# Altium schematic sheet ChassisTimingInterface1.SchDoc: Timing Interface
size B; Engineer: Daniel Sigg; DocumentNumber: 1; Revision: C; SheetNumber: 1; SheetTotal: 12; PageSetup: Record=PageOptions¦CenterHorizontal=True¦CenterVertical=True¦PrintScale=0.72¦XCorrection=1.00¦YCorrection=1.00¦PrintKind=0¦BorderSize=5000000¦LeftOffset=0¦BottomOffset=0¦Orientation=2¦PaperLength=1000¦PaperWidth=1000¦Scale=100¦PaperSource=7¦PrintQuality=-4¦MediaType=1¦DitherType=10¦PaperKind=Tabloid¦PrintScaleMode=1
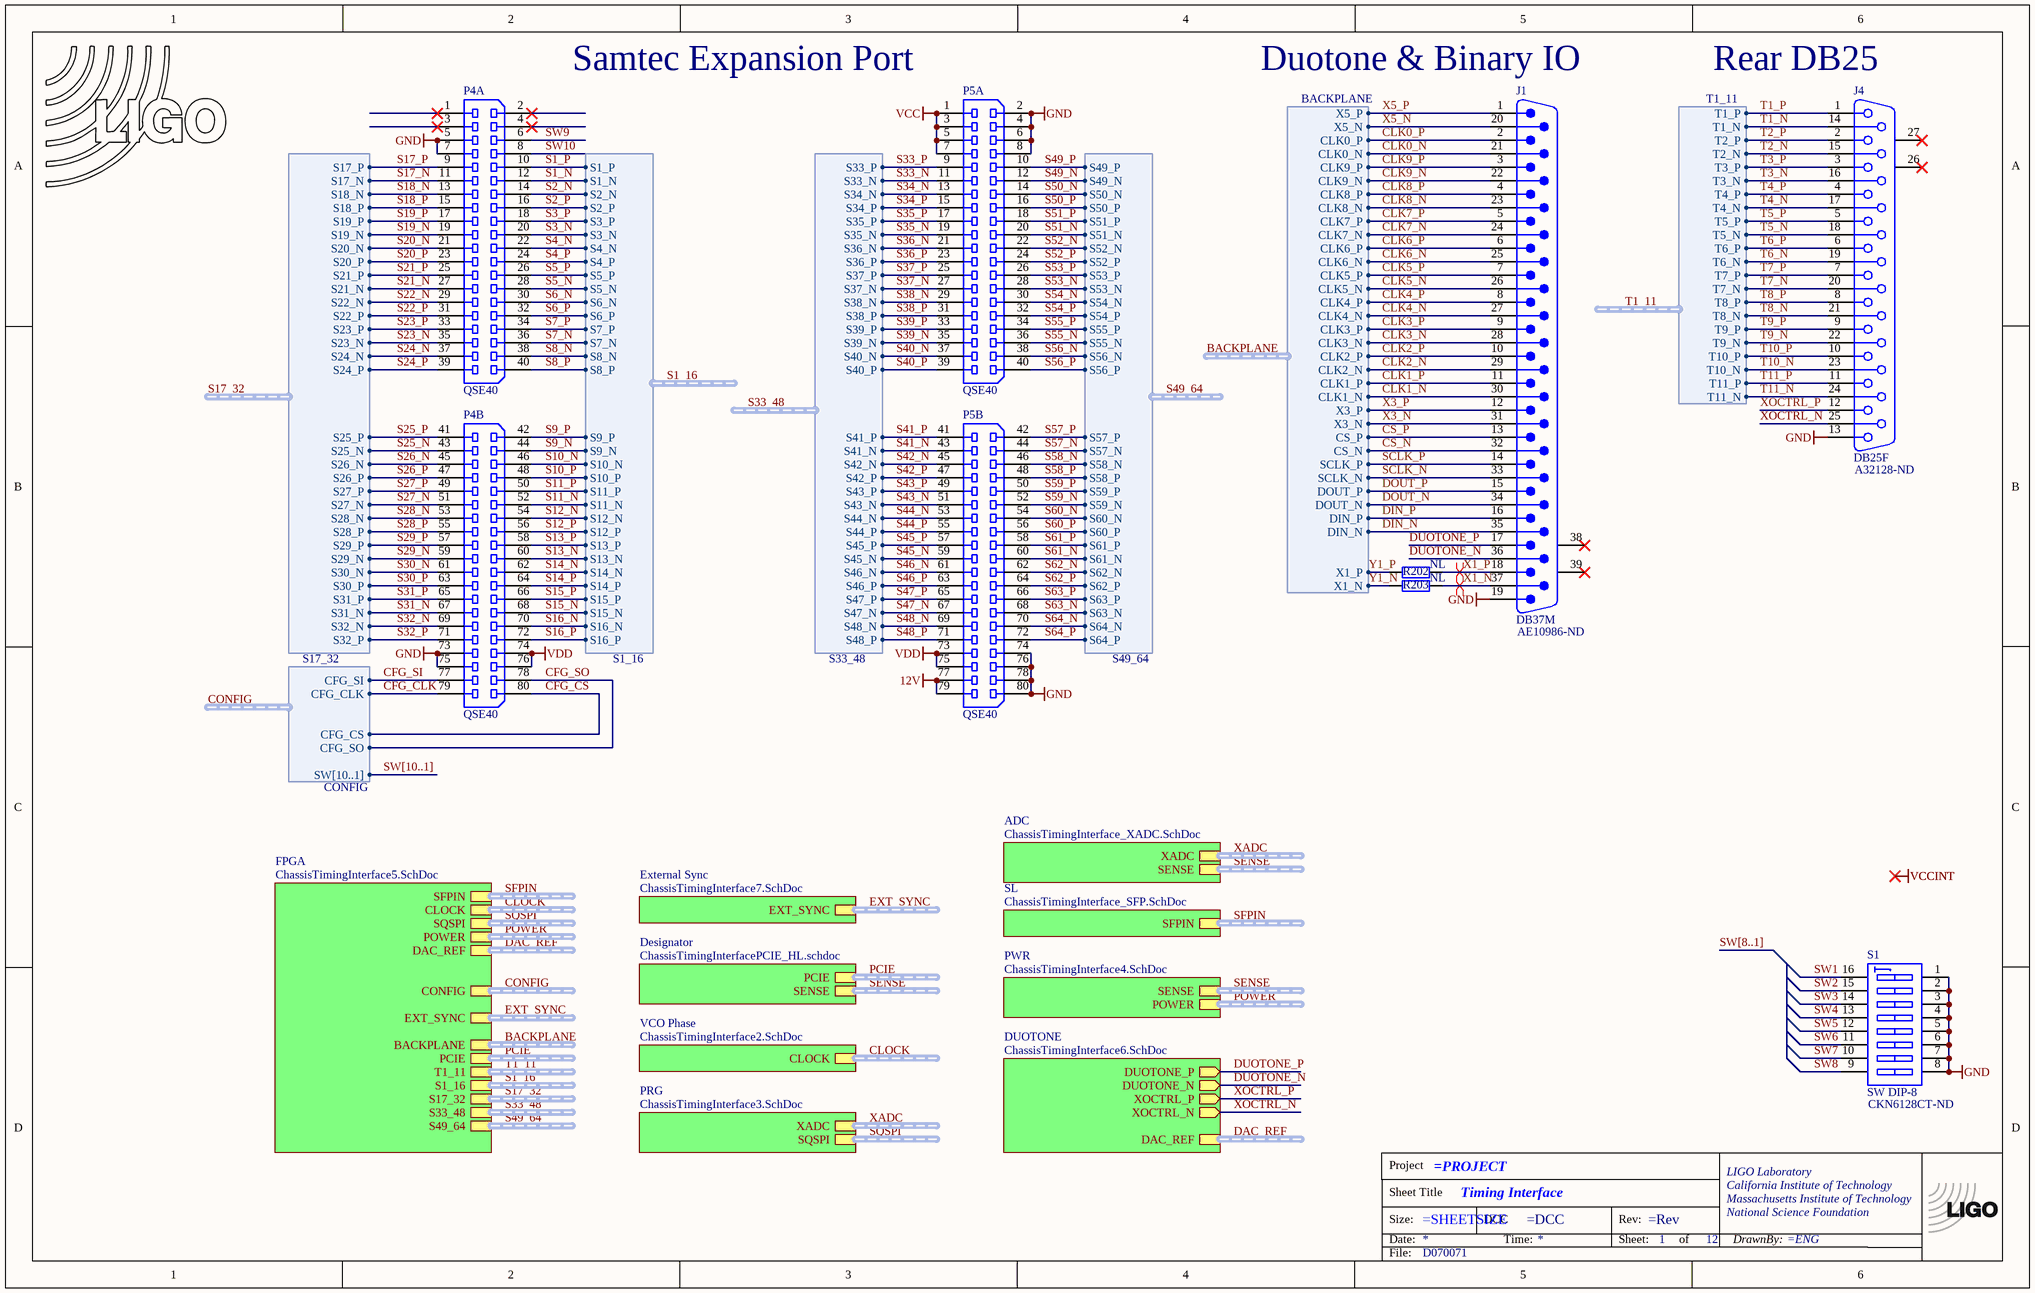
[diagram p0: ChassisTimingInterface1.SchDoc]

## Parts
*  TitleBlock  (value not drawn)  (graphical)
J1  DB37M  Supplier Part Number 1: AE10986-ND  [DB37M-RA]
J4  DB25F  Supplier Part Number 1: A32128-ND  [DB25F-RA]
LOGO1  LIGO logo  [LIGO-LOGO-SM]  (value not drawn)  (no BOM)
P4  QSE40  [QSE040]  (parts A,B of 2)
P5  QSE40  [QSE040]  (parts A,B of 2)
R202  NL  [CR1005-0402]
R203  NL  [CR1005-0402]
S1  SW DIP-8  Supplier Part Number 1: CKN6128CT-ND  [DIP_SW_8WAY_SMD_SIDE]

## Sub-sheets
ADC = ChassisTimingInterface_XADC.SchDoc: XADC (harness XADC), SENSE (harness SENSE)
Designator = ChassisTimingInterfacePCIE_HL.schdoc: PCIE (harness PCIE), SENSE (harness SENSE)
DUOTONE = ChassisTimingInterface6.SchDoc: DUOTONE_N (out), DUOTONE_P (out), XOCTRL_P (out), XOCTRL_N (out), DAC_REF (harness DAC_REF)
External Sync = ChassisTimingInterface7.SchDoc: EXT_SYNC (harness EXT_SYNC)
FPGA = ChassisTimingInterface5.SchDoc: S1_16 (harness S1_16), S17_32 (harness S17_32), S33_48 (harness S33_48), S49_64 (harness S49_64), T1_11 (harness T1_11), CLOCK (harness CLOCK), PCIE (harness PCIE), POWER (harness POWER), SQSPI (harness SQSPI), DAC_REF (harness DAC_REF), CONFIG (harness CONFIG), BACKPLANE (harness BACKPLANE), SFPIN (harness SFPIN), EXT_SYNC (harness EXT_SYNC)
PRG = ChassisTimingInterface3.SchDoc: SQSPI (harness SQSPI), XADC (harness XADC)
PWR = ChassisTimingInterface4.SchDoc: POWER (harness POWER), SENSE (harness SENSE)
SL = ChassisTimingInterface_SFP.SchDoc: SFPIN (harness SFPIN)
VCO Phase = ChassisTimingInterface2.SchDoc: CLOCK (harness CLOCK)

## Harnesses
S1_16: S1_N, S1_P, S2_N, S2_P, S3_N, S3_P, S4_N, S4_P, S5_N, S5_P, S6_N, S6_P, S7_N, S7_P, S8_N, S8_P, S9_N, S9_P, S10_N, S10_P, S11_N, S11_P, S12_N, S12_P, S13_N, S13_P, S14_N, S14_P, S15_N, S15_P, S16_N, S16_P
S17_32: S17_N, S17_P, S18_N, S18_P, S19_N, S19_P, S20_N, S20_P, S21_N, S21_P, S22_N, S22_P, S23_N, S23_P, S24_N, S24_P, S25_N, S25_P, S26_N, S26_P, S27_N, S27_P, S28_N, S28_P, S29_N, S29_P, S30_N, S30_P, S31_N, S31_P, S32_N, S32_P
S33_48: S33_P, S33_N, S34_P, S34_N, S35_P, S35_N, S36_N, S36_P, S37_P, S37_N, S38_N, S38_P, S39_P, S39_N, S40_N, S40_P, S41_P, S41_N, S42_N, S42_P, S43_P, S43_N, S44_N, S44_P, S45_P, S45_N, S46_N, S46_P, S47_P, S47_N, S48_N, S48_P
S49_64: S49_P, S49_N, S50_N, S50_P, S51_P, S51_N, S52_N, S52_P, S53_P, S53_N, S54_N, S54_P, S55_P, S55_N, S56_N, S56_P, S57_P, S57_N, S58_N, S58_P, S59_P, S59_N, S60_N, S60_P, S61_P, S61_N, S62_N, S62_P, S63_P, S63_N, S64_N, S64_P
T1_11: T1_P, T1_N, T2_P, T2_N, T3_P, T3_N, T4_P, T4_N, T5_P, T5_N, T6_P, T6_N, T7_P, T7_N, T8_P, T8_N, T9_P, T9_N, T10_P, T10_N, T11_P, T11_N
CONFIG: CFG_CLK, CFG_CS, CFG_SI, CFG_SO, SW[10..1]
BACKPLANE: DIN_N, DIN_P, DOUT_N, DOUT_P, SCLK_N, SCLK_P, CS_N, CS_P, X3_N, X3_P, CLK1_N, CLK1_P, CLK2_N, CLK2_P, CLK3_N, CLK3_P, CLK4_N, CLK4_P, CLK5_N, CLK5_P, CLK6_N, CLK6_P, CLK7_N, CLK7_P, CLK8_N, CLK8_P, CLK9_N, CLK9_P, CLK0_N, CLK0_P, X5_N, X5_P, X1_P, X1_N

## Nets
12V: P5.77 P5.79
GND: J1.19 J4.13 P4.5 P4.7 P4.73 P4.75 P4.81 P4.82 P4.83 P4.84 P4.85 P4.86 P4.87 P4.88 P5.2 P5.4 P5.6 P5.8 P5.74 P5.76 P5.78 P5.80 P5.81 P5.82 P5.83 P5.84 P5.85 P5.86 P5.87 P5.88 S1.1(A1) S1.2(A2) S1.3(A3) S1.4(A4) S1.5(A5) S1.6(A6) S1.7(A7) S1.8(A8)
VCC: P5.1 P5.3 P5.5 P5.7
VDD: P4.74 P4.76 P5.73 P5.75
CFG_CLK: P4.79 ; sheet FPGA/CONFIG.CFG_CLK
CFG_CS: P4.80 ; sheet FPGA/CONFIG.CFG_CS
CFG_SI: P4.77 ; sheet FPGA/CONFIG.CFG_SI
CFG_SO: P4.78 ; sheet FPGA/CONFIG.CFG_SO
CLK0_N: J1.21 ; sheet FPGA/BACKPLANE.CLK0_N  [project net BACKPLANE.CLK0_N]
CLK0_P: J1.2 ; sheet FPGA/BACKPLANE.CLK0_P  [project net BACKPLANE.CLK0_P]
CLK1_N: J1.30 ; sheet FPGA/BACKPLANE.CLK1_N  [project net BACKPLANE.CLK1_N]
CLK1_P: J1.11 ; sheet FPGA/BACKPLANE.CLK1_P  [project net BACKPLANE.CLK1_P]
CLK2_N: J1.29 ; sheet FPGA/BACKPLANE.CLK2_N  [project net BACKPLANE.CLK2_N]
CLK2_P: J1.10 ; sheet FPGA/BACKPLANE.CLK2_P  [project net BACKPLANE.CLK2_P]
CLK3_N: J1.28 ; sheet FPGA/BACKPLANE.CLK3_N  [project net BACKPLANE.CLK3_N]
CLK3_P: J1.9 ; sheet FPGA/BACKPLANE.CLK3_P  [project net BACKPLANE.CLK3_P]
CLK4_N: J1.27 ; sheet FPGA/BACKPLANE.CLK4_N  [project net BACKPLANE.CLK4_N]
CLK4_P: J1.8 ; sheet FPGA/BACKPLANE.CLK4_P  [project net BACKPLANE.CLK4_P]
CLK5_N: J1.26 ; sheet FPGA/BACKPLANE.CLK5_N  [project net BACKPLANE.CLK5_N]
CLK5_P: J1.7 ; sheet FPGA/BACKPLANE.CLK5_P  [project net BACKPLANE.CLK5_P]
CLK6_N: J1.25 ; sheet FPGA/BACKPLANE.CLK6_N  [project net BACKPLANE.CLK6_N]
CLK6_P: J1.6 ; sheet FPGA/BACKPLANE.CLK6_P  [project net BACKPLANE.CLK6_P]
CLK7_N: J1.24 ; sheet FPGA/BACKPLANE.CLK7_N  [project net BACKPLANE.CLK7_N]
CLK7_P: J1.5 ; sheet FPGA/BACKPLANE.CLK7_P  [project net BACKPLANE.CLK7_P]
CLK8_N: J1.23 ; sheet FPGA/BACKPLANE.CLK8_N  [project net BACKPLANE.CLK8_N]
CLK8_P: J1.4 ; sheet FPGA/BACKPLANE.CLK8_P  [project net BACKPLANE.CLK8_P]
CLK9_N: J1.22 ; sheet FPGA/BACKPLANE.CLK9_N  [project net BACKPLANE.CLK9_N]
CLK9_P: J1.3 ; sheet FPGA/BACKPLANE.CLK9_P  [project net BACKPLANE.CLK9_P]
CS_N: J1.32 ; sheet FPGA/BACKPLANE.CS_N  [project net BACKPLANE.CS_N]
CS_P: J1.13 ; sheet FPGA/BACKPLANE.CS_P  [project net BACKPLANE.CS_P]
DIN_N: J1.35 ; sheet FPGA/BACKPLANE.DIN_N  [project net BACKPLANE.DIN_N]
DIN_P: J1.16 ; sheet FPGA/BACKPLANE.DIN_P  [project net BACKPLANE.DIN_P]
DOUT_N: J1.34 ; sheet FPGA/BACKPLANE.DOUT_N  [project net BACKPLANE.DOUT_N]
DOUT_P: J1.15 ; sheet FPGA/BACKPLANE.DOUT_P  [project net BACKPLANE.DOUT_P]
DUOTONE_N: J1.36 ; sheet DUOTONE/DUOTONE_N
DUOTONE_P: J1.17 ; sheet DUOTONE/DUOTONE_P
S1_N: P4.12 ; sheet FPGA/S1_16.S1_N  [project net S1_16.S1_N]
S1_P: P4.10 ; sheet FPGA/S1_16.S1_P  [project net S1_16.S1_P]
S2_N: P4.14 ; sheet FPGA/S1_16.S2_N  [project net S1_16.S2_N]
S2_P: P4.16 ; sheet FPGA/S1_16.S2_P  [project net S1_16.S2_P]
S3_N: P4.20 ; sheet FPGA/S1_16.S3_N  [project net S1_16.S3_N]
S3_P: P4.18 ; sheet FPGA/S1_16.S3_P  [project net S1_16.S3_P]
S4_N: P4.22 ; sheet FPGA/S1_16.S4_N  [project net S1_16.S4_N]
S4_P: P4.24 ; sheet FPGA/S1_16.S4_P  [project net S1_16.S4_P]
S5_N: P4.28 ; sheet FPGA/S1_16.S5_N  [project net S1_16.S5_N]
S5_P: P4.26 ; sheet FPGA/S1_16.S5_P  [project net S1_16.S5_P]
S6_N: P4.30 ; sheet FPGA/S1_16.S6_N  [project net S1_16.S6_N]
S6_P: P4.32 ; sheet FPGA/S1_16.S6_P  [project net S1_16.S6_P]
S7_N: P4.36 ; sheet FPGA/S1_16.S7_N  [project net S1_16.S7_N]
S7_P: P4.34 ; sheet FPGA/S1_16.S7_P  [project net S1_16.S7_P]
S8_N: P4.38 ; sheet FPGA/S1_16.S8_N  [project net S1_16.S8_N]
S8_P: P4.40 ; sheet FPGA/S1_16.S8_P  [project net S1_16.S8_P]
S9_N: P4.44 ; sheet FPGA/S1_16.S9_N  [project net S1_16.S9_N]
S9_P: P4.42 ; sheet FPGA/S1_16.S9_P  [project net S1_16.S9_P]
S10_N: P4.46 ; sheet FPGA/S1_16.S10_N
S10_P: P4.48 ; sheet FPGA/S1_16.S10_P
S11_N: P4.52 ; sheet FPGA/S1_16.S11_N
S11_P: P4.50 ; sheet FPGA/S1_16.S11_P
S12_N: P4.54 ; sheet FPGA/S1_16.S12_N
S12_P: P4.56 ; sheet FPGA/S1_16.S12_P
S13_N: P4.60 ; sheet FPGA/S1_16.S13_N
S13_P: P4.58 ; sheet FPGA/S1_16.S13_P
S14_N: P4.62 ; sheet FPGA/S1_16.S14_N
S14_P: P4.64 ; sheet FPGA/S1_16.S14_P
S15_N: P4.68 ; sheet FPGA/S1_16.S15_N
S15_P: P4.66 ; sheet FPGA/S1_16.S15_P
S16_N: P4.70 ; sheet FPGA/S1_16.S16_N
S16_P: P4.72 ; sheet FPGA/S1_16.S16_P
S17_N: P4.11 ; sheet FPGA/S17_32.S17_N  [project net S17_32.S17_N]
S17_P: P4.9 ; sheet FPGA/S17_32.S17_P  [project net S17_32.S17_P]
S18_N: P4.13 ; sheet FPGA/S17_32.S18_N  [project net S17_32.S18_N]
S18_P: P4.15 ; sheet FPGA/S17_32.S18_P  [project net S17_32.S18_P]
S19_N: P4.19 ; sheet FPGA/S17_32.S19_N  [project net S17_32.S19_N]
S19_P: P4.17 ; sheet FPGA/S17_32.S19_P  [project net S17_32.S19_P]
S20_N: P4.21 ; sheet FPGA/S17_32.S20_N  [project net S17_32.S20_N]
S20_P: P4.23 ; sheet FPGA/S17_32.S20_P  [project net S17_32.S20_P]
S21_N: P4.27 ; sheet FPGA/S17_32.S21_N  [project net S17_32.S21_N]
S21_P: P4.25 ; sheet FPGA/S17_32.S21_P  [project net S17_32.S21_P]
S22_N: P4.29 ; sheet FPGA/S17_32.S22_N  [project net S17_32.S22_N]
S22_P: P4.31 ; sheet FPGA/S17_32.S22_P  [project net S17_32.S22_P]
S23_N: P4.35 ; sheet FPGA/S17_32.S23_N  [project net S17_32.S23_N]
S23_P: P4.33 ; sheet FPGA/S17_32.S23_P  [project net S17_32.S23_P]
S24_N: P4.37 ; sheet FPGA/S17_32.S24_N  [project net S17_32.S24_N]
S24_P: P4.39 ; sheet FPGA/S17_32.S24_P  [project net S17_32.S24_P]
S25_N: P4.43 ; sheet FPGA/S17_32.S25_N  [project net S17_32.S25_N]
S25_P: P4.41 ; sheet FPGA/S17_32.S25_P  [project net S17_32.S25_P]
S26_N: P4.45 ; sheet FPGA/S17_32.S26_N  [project net S17_32.S26_N]
S26_P: P4.47 ; sheet FPGA/S17_32.S26_P  [project net S17_32.S26_P]
S27_N: P4.51 ; sheet FPGA/S17_32.S27_N  [project net S17_32.S27_N]
S27_P: P4.49 ; sheet FPGA/S17_32.S27_P  [project net S17_32.S27_P]
S28_N: P4.53 ; sheet FPGA/S17_32.S28_N  [project net S17_32.S28_N]
S28_P: P4.55 ; sheet FPGA/S17_32.S28_P  [project net S17_32.S28_P]
S29_N: P4.59 ; sheet FPGA/S17_32.S29_N  [project net S17_32.S29_N]
S29_P: P4.57 ; sheet FPGA/S17_32.S29_P  [project net S17_32.S29_P]
S30_N: P4.61 ; sheet FPGA/S17_32.S30_N  [project net S17_32.S30_N]
S30_P: P4.63 ; sheet FPGA/S17_32.S30_P  [project net S17_32.S30_P]
S31_N: P4.67 ; sheet FPGA/S17_32.S31_N  [project net S17_32.S31_N]
S31_P: P4.65 ; sheet FPGA/S17_32.S31_P  [project net S17_32.S31_P]
S32_N: P4.69 ; sheet FPGA/S17_32.S32_N  [project net S17_32.S32_N]
S32_P: P4.71 ; sheet FPGA/S17_32.S32_P  [project net S17_32.S32_P]
S33_N: P5.11 ; sheet FPGA/S33_48.S33_N  [project net S33_48.S33_N]
S33_P: P5.9 ; sheet FPGA/S33_48.S33_P  [project net S33_48.S33_P]
S34_N: P5.13 ; sheet FPGA/S33_48.S34_N  [project net S33_48.S34_N]
S34_P: P5.15 ; sheet FPGA/S33_48.S34_P  [project net S33_48.S34_P]
S35_N: P5.19 ; sheet FPGA/S33_48.S35_N  [project net S33_48.S35_N]
S35_P: P5.17 ; sheet FPGA/S33_48.S35_P  [project net S33_48.S35_P]
S36_N: P5.21 ; sheet FPGA/S33_48.S36_N  [project net S33_48.S36_N]
S36_P: P5.23 ; sheet FPGA/S33_48.S36_P  [project net S33_48.S36_P]
S37_N: P5.27 ; sheet FPGA/S33_48.S37_N  [project net S33_48.S37_N]
S37_P: P5.25 ; sheet FPGA/S33_48.S37_P  [project net S33_48.S37_P]
S38_N: P5.29 ; sheet FPGA/S33_48.S38_N  [project net S33_48.S38_N]
S38_P: P5.31 ; sheet FPGA/S33_48.S38_P  [project net S33_48.S38_P]
S39_N: P5.35 ; sheet FPGA/S33_48.S39_N  [project net S33_48.S39_N]
S39_P: P5.33 ; sheet FPGA/S33_48.S39_P  [project net S33_48.S39_P]
S40_N: P5.37 ; sheet FPGA/S33_48.S40_N  [project net S33_48.S40_N]
S40_P: P5.39 ; sheet FPGA/S33_48.S40_P  [project net S33_48.S40_P]
S41_N: P5.43 ; sheet FPGA/S33_48.S41_N  [project net S33_48.S41_N]
S41_P: P5.41 ; sheet FPGA/S33_48.S41_P  [project net S33_48.S41_P]
S42_N: P5.45 ; sheet FPGA/S33_48.S42_N  [project net S33_48.S42_N]
S42_P: P5.47 ; sheet FPGA/S33_48.S42_P  [project net S33_48.S42_P]
S43_N: P5.51 ; sheet FPGA/S33_48.S43_N  [project net S33_48.S43_N]
S43_P: P5.49 ; sheet FPGA/S33_48.S43_P  [project net S33_48.S43_P]
S44_N: P5.53 ; sheet FPGA/S33_48.S44_N  [project net S33_48.S44_N]
S44_P: P5.55 ; sheet FPGA/S33_48.S44_P  [project net S33_48.S44_P]
S45_N: P5.59 ; sheet FPGA/S33_48.S45_N  [project net S33_48.S45_N]
S45_P: P5.57 ; sheet FPGA/S33_48.S45_P  [project net S33_48.S45_P]
S46_N: P5.61 ; sheet FPGA/S33_48.S46_N  [project net S33_48.S46_N]
S46_P: P5.63 ; sheet FPGA/S33_48.S46_P  [project net S33_48.S46_P]
S47_N: P5.67 ; sheet FPGA/S33_48.S47_N  [project net S33_48.S47_N]
S47_P: P5.65 ; sheet FPGA/S33_48.S47_P  [project net S33_48.S47_P]
S48_N: P5.69 ; sheet FPGA/S33_48.S48_N  [project net S33_48.S48_N]
S48_P: P5.71 ; sheet FPGA/S33_48.S48_P  [project net S33_48.S48_P]
S49_N: P5.12 ; sheet FPGA/S49_64.S49_N  [project net S49_64.S49_N]
S49_P: P5.10 ; sheet FPGA/S49_64.S49_P  [project net S49_64.S49_P]
S50_N: P5.14 ; sheet FPGA/S49_64.S50_N  [project net S49_64.S50_N]
S50_P: P5.16 ; sheet FPGA/S49_64.S50_P  [project net S49_64.S50_P]
S51_N: P5.20 ; sheet FPGA/S49_64.S51_N  [project net S49_64.S51_N]
S51_P: P5.18 ; sheet FPGA/S49_64.S51_P  [project net S49_64.S51_P]
S52_N: P5.22 ; sheet FPGA/S49_64.S52_N  [project net S49_64.S52_N]
S52_P: P5.24 ; sheet FPGA/S49_64.S52_P  [project net S49_64.S52_P]
S53_N: P5.28 ; sheet FPGA/S49_64.S53_N  [project net S49_64.S53_N]
S53_P: P5.26 ; sheet FPGA/S49_64.S53_P  [project net S49_64.S53_P]
S54_N: P5.30 ; sheet FPGA/S49_64.S54_N  [project net S49_64.S54_N]
S54_P: P5.32 ; sheet FPGA/S49_64.S54_P  [project net S49_64.S54_P]
S55_N: P5.36 ; sheet FPGA/S49_64.S55_N  [project net S49_64.S55_N]
S55_P: P5.34 ; sheet FPGA/S49_64.S55_P  [project net S49_64.S55_P]
S56_N: P5.38 ; sheet FPGA/S49_64.S56_N  [project net S49_64.S56_N]
S56_P: P5.40 ; sheet FPGA/S49_64.S56_P  [project net S49_64.S56_P]
S57_N: P5.44 ; sheet FPGA/S49_64.S57_N  [project net S49_64.S57_N]
S57_P: P5.42 ; sheet FPGA/S49_64.S57_P  [project net S49_64.S57_P]
S58_N: P5.46 ; sheet FPGA/S49_64.S58_N  [project net S49_64.S58_N]
S58_P: P5.48 ; sheet FPGA/S49_64.S58_P  [project net S49_64.S58_P]
S59_N: P5.52 ; sheet FPGA/S49_64.S59_N  [project net S49_64.S59_N]
S59_P: P5.50 ; sheet FPGA/S49_64.S59_P  [project net S49_64.S59_P]
S60_N: P5.54 ; sheet FPGA/S49_64.S60_N  [project net S49_64.S60_N]
S60_P: P5.56 ; sheet FPGA/S49_64.S60_P  [project net S49_64.S60_P]
S61_N: P5.60 ; sheet FPGA/S49_64.S61_N  [project net S49_64.S61_N]
S61_P: P5.58 ; sheet FPGA/S49_64.S61_P  [project net S49_64.S61_P]
S62_N: P5.62 ; sheet FPGA/S49_64.S62_N  [project net S49_64.S62_N]
S62_P: P5.64 ; sheet FPGA/S49_64.S62_P  [project net S49_64.S62_P]
S63_N: P5.68 ; sheet FPGA/S49_64.S63_N  [project net S49_64.S63_N]
S63_P: P5.66 ; sheet FPGA/S49_64.S63_P  [project net S49_64.S63_P]
S64_N: P5.70 ; sheet FPGA/S49_64.S64_N  [project net S49_64.S64_N]
S64_P: P5.72 ; sheet FPGA/S49_64.S64_P  [project net S49_64.S64_P]
SCLK_N: J1.33 ; sheet FPGA/BACKPLANE.SCLK_N  [project net BACKPLANE.SCLK_N]
SCLK_P: J1.14 ; sheet FPGA/BACKPLANE.SCLK_P  [project net BACKPLANE.SCLK_P]
SW1: S1.16(B1)
SW2: S1.15(B2)
SW3: S1.14(B3)
SW4: S1.13(B4)
SW5: S1.12(B5)
SW6: S1.11(B6)
SW7: S1.10(B7)
SW8: S1.9(B8)
SW9: P4.6
SW10: P4.8
T1_N: J4.14 ; sheet FPGA/T1_11.T1_N  [project net T1_11.T1_N]
T1_P: J4.1 ; sheet FPGA/T1_11.T1_P  [project net T1_11.T1_P]
T2_N: J4.15 ; sheet FPGA/T1_11.T2_N  [project net T1_11.T2_N]
T2_P: J4.2 ; sheet FPGA/T1_11.T2_P  [project net T1_11.T2_P]
T3_N: J4.16 ; sheet FPGA/T1_11.T3_N  [project net T1_11.T3_N]
T3_P: J4.3 ; sheet FPGA/T1_11.T3_P  [project net T1_11.T3_P]
T4_N: J4.17 ; sheet FPGA/T1_11.T4_N  [project net T1_11.T4_N]
T4_P: J4.4 ; sheet FPGA/T1_11.T4_P  [project net T1_11.T4_P]
T5_N: J4.18 ; sheet FPGA/T1_11.T5_N  [project net T1_11.T5_N]
T5_P: J4.5 ; sheet FPGA/T1_11.T5_P  [project net T1_11.T5_P]
T6_N: J4.19 ; sheet FPGA/T1_11.T6_N  [project net T1_11.T6_N]
T6_P: J4.6 ; sheet FPGA/T1_11.T6_P  [project net T1_11.T6_P]
T7_N: J4.20 ; sheet FPGA/T1_11.T7_N  [project net T1_11.T7_N]
T7_P: J4.7 ; sheet FPGA/T1_11.T7_P  [project net T1_11.T7_P]
T8_N: J4.21 ; sheet FPGA/T1_11.T8_N  [project net T1_11.T8_N]
T8_P: J4.8 ; sheet FPGA/T1_11.T8_P  [project net T1_11.T8_P]
T9_N: J4.22 ; sheet FPGA/T1_11.T9_N  [project net T1_11.T9_N]
T9_P: J4.9 ; sheet FPGA/T1_11.T9_P  [project net T1_11.T9_P]
T10_N: J4.23 ; sheet FPGA/T1_11.T10_N
T10_P: J4.10 ; sheet FPGA/T1_11.T10_P
T11_N: J4.24 ; sheet FPGA/T1_11.T11_N
T11_P: J4.11 ; sheet FPGA/T1_11.T11_P
X1_N: J1.37 R203.2
X1_P: J1.18 R202.2
X3_N: J1.31 ; sheet FPGA/BACKPLANE.X3_N  [project net BACKPLANE.X3_N]
X3_P: J1.12 ; sheet FPGA/BACKPLANE.X3_P  [project net BACKPLANE.X3_P]
X5_N: J1.20 ; sheet FPGA/BACKPLANE.X5_N  [project net BACKPLANE.X5_N]
X5_P: J1.1 ; sheet FPGA/BACKPLANE.X5_P  [project net BACKPLANE.X5_P]
XOCTRL_N: J4.25 ; sheet DUOTONE/XOCTRL_N
XOCTRL_P: J4.12 ; sheet DUOTONE/XOCTRL_P
Y1_N: R203.1 ; sheet FPGA/BACKPLANE.X1_N  [project net BACKPLANE.X1_N]
Y1_P: R202.1 ; sheet FPGA/BACKPLANE.X1_P  [project net BACKPLANE.X1_P]

Not connected (* = marked no-connect by the designer): J1 38* 39*; J4 26(MH1)* 27(MH2)*; P4 1* 2* 3* 4*

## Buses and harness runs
bus SW[8..1]
bus SW[10..1]
harness BACKPLANE = sheet FPGA/BACKPLANE
harness CLOCK = sheet FPGA/CLOCK
harness CLOCK = sheet VCO Phase/CLOCK
harness CONFIG = sheet FPGA/CONFIG
harness DAC_REF = sheet DUOTONE/DAC_REF
harness DAC_REF = sheet FPGA/DAC_REF
harness EXT_SYNC = sheet External Sync/EXT_SYNC
harness EXT_SYNC = sheet FPGA/EXT_SYNC
harness PCIE = sheet Designator/PCIE
harness PCIE = sheet FPGA/PCIE
harness POWER = sheet FPGA/POWER
harness POWER = sheet PWR/POWER
harness S1_16 = sheet FPGA/S1_16
harness S17_32 = sheet FPGA/S17_32
harness S33_48 = sheet FPGA/S33_48
harness S49_64 = sheet FPGA/S49_64
harness SENSE = sheet ADC/SENSE
harness SENSE = sheet Designator/SENSE
harness SENSE = sheet PWR/SENSE
harness SFPIN = sheet FPGA/SFPIN
harness SFPIN = sheet SL/SFPIN
harness SQSPI = sheet FPGA/SQSPI
harness SQSPI = sheet PRG/SQSPI
harness T1_11 = sheet FPGA/T1_11
harness XADC = sheet ADC/XADC
harness XADC = sheet PRG/XADC

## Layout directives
differential pair: X1_N, X1_P

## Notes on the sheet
- (near P5) Samtec Expansion Port
- (near J1) Duotone & Binary IO
- (near J4) Rear DB25

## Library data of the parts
J1 = DB37M: Plug Assembly, 37 Position, Right Angle, .318 Series; Part Number: A32104-ND
J4 = DB25F: Receptacle Assembly, 25 Position, Right Angle, .318 Series
LOGO1 = LIGO_logo
P4 P5 = SAMTEC_QSE40: Samtec hi-speed socket, 0.8mm, 80 pins; Part Number: SAM8124-ND
R202 R203 = ChipRes1: Resistor, surface mount; Tolerance: 0.1%
S1 = SW DIP-8: DIP Switch, 8 Position, SPST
